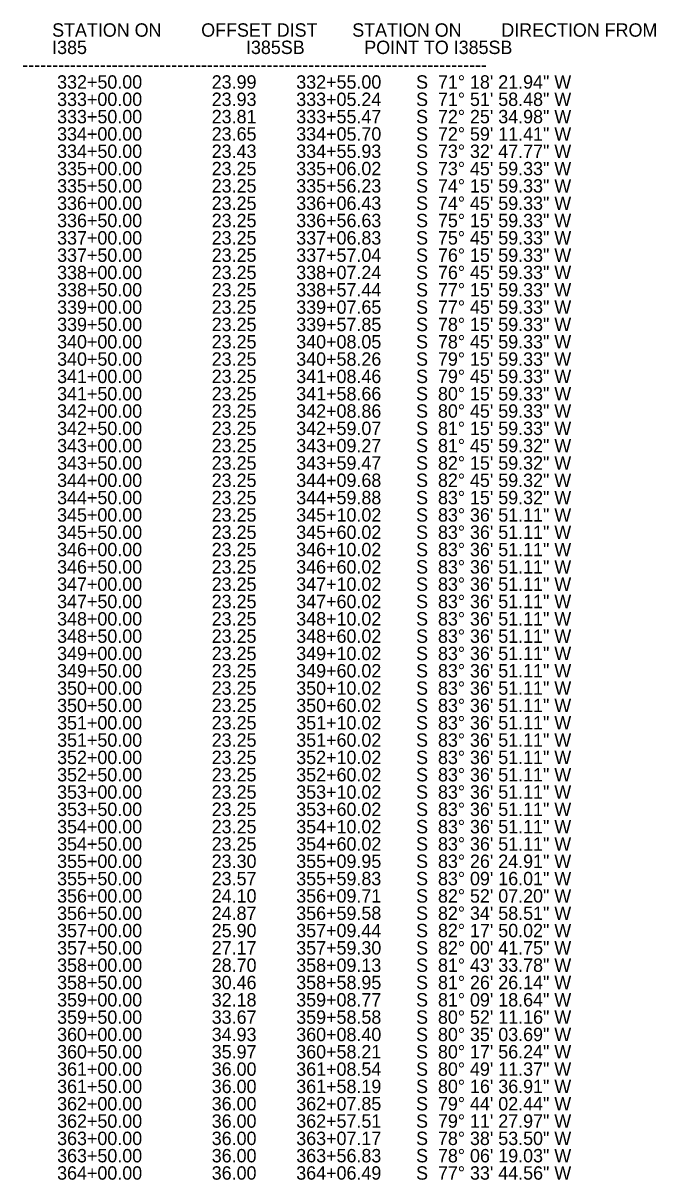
# Model space of a CAD drawing. Extents: x 1602163 to 1612907, y 1087635 to 1096265.
# Drawn here: x 1602163 to 1602447, y 1095622 to 1096141 of the extents above; entities that cross this region are included whole.
import ezdxf

# ---------------------------------------------------------------- set-up
doc = ezdxf.new("R2010")
doc.units = 0
doc.layers.add('RD_SHT_TX', color=7, linetype='Continuous')

msp = doc.modelspace()

# ---------------------------------------------------------------- texts
at = {"layer": 'RD_SHT_TX'}
for s, p in [('      STATION ON        OFFSET DIST       STATION ON        DIRECTION FROM', (1602162.4, 1096134.97)), ('      I385                                I385SB            POINT TO I385SB', (1602162.4, 1096127.2)), ('------------------------------------------------------------------------------', (1602162.4, 1096119.43)), ('       332+50.00              23.99        332+55.00       S  71° 18\' 21.94" W  ', (1602162.4, 1096111.67)), ('       333+00.00              23.93        333+05.24       S  71° 51\' 58.48" W  ', (1602162.4, 1096103.9)), ('       333+50.00              23.81        333+55.47       S  72° 25\' 34.98" W  ', (1602162.4, 1096096.14)), ('       334+00.00              23.65        334+05.70       S  72° 59\' 11.41" W  ', (1602162.4, 1096088.37)), ('       334+50.00              23.43        334+55.93       S  73° 32\' 47.77" W  ', (1602162.4, 1096080.61)), ('       335+00.00              23.25        335+06.02       S  73° 45\' 59.33" W  ', (1602162.4, 1096072.84)), ('       335+50.00              23.25        335+56.23       S  74° 15\' 59.33" W  ', (1602162.4, 1096065.08)), ('       336+00.00              23.25        336+06.43       S  74° 45\' 59.33" W  ', (1602162.4, 1096057.31)), ('       336+50.00              23.25        336+56.63       S  75° 15\' 59.33" W  ', (1602162.4, 1096049.55)), ('       337+00.00              23.25        337+06.83       S  75° 45\' 59.33" W  ', (1602162.4, 1096041.78)), ('       337+50.00              23.25        337+57.04       S  76° 15\' 59.33" W  ', (1602162.4, 1096034.02)), ('       338+00.00              23.25        338+07.24       S  76° 45\' 59.33" W  ', (1602162.4, 1096026.25)), ('       338+50.00              23.25        338+57.44       S  77° 15\' 59.33" W  ', (1602162.4, 1096018.49)), ('       339+00.00              23.25        339+07.65       S  77° 45\' 59.33" W  ', (1602162.4, 1096010.72)), ('       339+50.00              23.25        339+57.85       S  78° 15\' 59.33" W  ', (1602162.4, 1096002.96)), ('       340+00.00              23.25        340+08.05       S  78° 45\' 59.33" W  ', (1602162.4, 1095995.19)), ('       340+50.00              23.25        340+58.26       S  79° 15\' 59.33" W  ', (1602162.4, 1095987.43)), ('       341+00.00              23.25        341+08.46       S  79° 45\' 59.33" W  ', (1602162.4, 1095979.66)), ('       341+50.00              23.25        341+58.66       S  80° 15\' 59.33" W  ', (1602162.4, 1095971.89)), ('       342+00.00              23.25        342+08.86       S  80° 45\' 59.33" W  ', (1602162.4, 1095964.13)), ('       342+50.00              23.25        342+59.07       S  81° 15\' 59.33" W  ', (1602162.4, 1095956.36)), ('       343+00.00              23.25        343+09.27       S  81° 45\' 59.32" W  ', (1602162.4, 1095948.6)), ('       343+50.00              23.25        343+59.47       S  82° 15\' 59.32" W  ', (1602162.4, 1095940.83)), ('       344+00.00              23.25        344+09.68       S  82° 45\' 59.32" W  ', (1602162.4, 1095933.07)), ('       344+50.00              23.25        344+59.88       S  83° 15\' 59.32" W  ', (1602162.4, 1095925.3)), ('       345+00.00              23.25        345+10.02       S  83° 36\' 51.11" W  ', (1602162.4, 1095917.54)), ('       345+50.00              23.25        345+60.02       S  83° 36\' 51.11" W  ', (1602162.4, 1095909.77)), ('       346+00.00              23.25        346+10.02       S  83° 36\' 51.11" W  ', (1602162.4, 1095902.01)), ('       346+50.00              23.25        346+60.02       S  83° 36\' 51.11" W  ', (1602162.4, 1095894.24)), ('       347+00.00              23.25        347+10.02       S  83° 36\' 51.11" W  ', (1602162.4, 1095886.48)), ('       347+50.00              23.25        347+60.02       S  83° 36\' 51.11" W  ', (1602162.4, 1095878.71)), ('       348+00.00              23.25        348+10.02       S  83° 36\' 51.11" W  ', (1602162.4, 1095870.95)), ('       348+50.00              23.25        348+60.02       S  83° 36\' 51.11" W  ', (1602162.4, 1095863.18)), ('       349+00.00              23.25        349+10.02       S  83° 36\' 51.11" W  ', (1602162.4, 1095855.42)), ('       349+50.00              23.25        349+60.02       S  83° 36\' 51.11" W  ', (1602162.4, 1095847.65)), ('       350+00.00              23.25        350+10.02       S  83° 36\' 51.11" W  ', (1602162.4, 1095839.89)), ('       350+50.00              23.25        350+60.02       S  83° 36\' 51.11" W  ', (1602162.4, 1095832.12)), ('       351+00.00              23.25        351+10.02       S  83° 36\' 51.11" W  ', (1602162.4, 1095824.36)), ('       351+50.00              23.25        351+60.02       S  83° 36\' 51.11" W  ', (1602162.4, 1095816.59)), ('       352+00.00              23.25        352+10.02       S  83° 36\' 51.11" W  ', (1602162.4, 1095808.82)), ('       352+50.00              23.25        352+60.02       S  83° 36\' 51.11" W  ', (1602162.4, 1095801.06)), ('       353+00.00              23.25        353+10.02       S  83° 36\' 51.11" W  ', (1602162.4, 1095793.29)), ('       353+50.00              23.25        353+60.02       S  83° 36\' 51.11" W  ', (1602162.4, 1095785.53)), ('       354+00.00              23.25        354+10.02       S  83° 36\' 51.11" W  ', (1602162.4, 1095777.76)), ('       354+50.00              23.25        354+60.02       S  83° 36\' 51.11" W  ', (1602162.4, 1095770)), ('       355+00.00              23.30        355+09.95       S  83° 26\' 24.91" W  ', (1602162.4, 1095762.23)), ('       355+50.00              23.57        355+59.83       S  83° 09\' 16.01" W  ', (1602162.4, 1095754.47)), ('       356+00.00              24.10        356+09.71       S  82° 52\' 07.20" W  ', (1602162.4, 1095746.7)), ('       356+50.00              24.87        356+59.58       S  82° 34\' 58.51" W  ', (1602162.4, 1095738.94)), ('       357+00.00              25.90        357+09.44       S  82° 17\' 50.02" W  ', (1602162.4, 1095731.17)), ('       357+50.00              27.17        357+59.30       S  82° 00\' 41.75" W  ', (1602162.4, 1095723.41)), ('       358+00.00              28.70        358+09.13       S  81° 43\' 33.78" W  ', (1602162.4, 1095715.64)), ('       358+50.00              30.46        358+58.95       S  81° 26\' 26.14" W  ', (1602162.4, 1095707.88)), ('       359+00.00              32.18        359+08.77       S  81° 09\' 18.64" W  ', (1602162.4, 1095700.11)), ('       359+50.00              33.67        359+58.58       S  80° 52\' 11.16" W  ', (1602162.4, 1095692.35)), ('       360+00.00              34.93        360+08.40       S  80° 35\' 03.69" W  ', (1602162.4, 1095684.58)), ('       360+50.00              35.97        360+58.21       S  80° 17\' 56.24" W  ', (1602162.4, 1095676.82)), ('       361+00.00              36.00        361+08.54       S  80° 49\' 11.37" W  ', (1602162.4, 1095669.05)), ('       361+50.00              36.00        361+58.19       S  80° 16\' 36.91" W  ', (1602162.4, 1095661.29)), ('       362+00.00              36.00        362+07.85       S  79° 44\' 02.44" W  ', (1602162.4, 1095653.52)), ('       362+50.00              36.00        362+57.51       S  79° 11\' 27.97" W  ', (1602162.4, 1095645.75)), ('       363+00.00              36.00        363+07.17       S  78° 38\' 53.50" W  ', (1602162.4, 1095637.99)), ('       363+50.00              36.00        363+56.83       S  78° 06\' 19.03" W  ', (1602162.4, 1095630.22)), ('       364+00.00              36.00        364+06.49       S  77° 33\' 44.56" W  ', (1602162.4, 1095622.46))]:
    msp.add_text(s, height=6, dxfattribs=at).set_placement(p)

doc.saveas('drawing.dxf')
